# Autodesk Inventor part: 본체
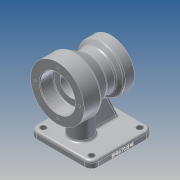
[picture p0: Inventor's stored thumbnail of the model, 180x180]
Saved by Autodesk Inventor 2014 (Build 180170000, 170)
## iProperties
Created: 2019-01
Part Number: 본체
Material: 알루미늄 6061
Document SubType Name: Modeling
Designer: kb542-15
Density: 2.71 g/cm^3
Appearance: 알루미늄 - 평지
Mass: 901.883 g
Surface Area: 599.891 cm^2
Volume: 332.798 cm^3
Author: kb542-15
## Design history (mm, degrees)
sketch "스케치1"
  geometry: L1 (0, 0)-(92, 0); L2 (92, 0)-(92, 92); L3 (92, 92)-(0, 92); L4 (0, 92)-(0, 0)
  constraints: 8 end point, 2 parallel, 1 horizontal, 1 perpendicular
  dimensions: "d0" = 92 distance between parallel lines of L2 L4; "d1" = 92 distance between parallel lines of L1 L3
extrude "돌출1" new body sketch "스케치1" distance "d2" = 10; taper "d3" = 0 deg
fillet "모깎기1" dims "d4" = 10
sketch "스케치3"
  geometry: L1 (82, 92)-(10, 92) reference; L2 (0, 82)-(0, 10) reference; L3 (10, 0)-(82, 0) reference; L4 (92, 10)-(92, 82) reference; C1 r 4.5 at (10, 82); C2 r 4.5 at (82, 82); C3 r 4.5 at (82, 10); C4 r 4.5 at (10, 10); A1 r 10 centre (10, 82) between (10, 92) and (0, 82) reference; A2 r 10 centre (82, 82) between (92, 82) and (82, 92) reference; A3 r 10 centre (82, 10) between (82, 0) and (92, 10) reference; A4 r 10 centre (10, 10) between (0, 10) and (10, 0) reference; 1 further point
  constraints: 4 centre point, 4 coincident, 3 equal radius
  dimensions: "d5" = 9 diameter of C1
extrude "돌출2" cut sketch "스케치3" distance "d6" = 10; taper "d7" = 0 deg
node "작업 평면1"
sketch "스케치4"
  geometry: L1 (-5, 80)-(75, 80); L2 (10, 0)-(82, 0) reference; L3 (0, 10)-(0, 0) reference; L4 (-5, 120)-(20, 120); L5 (20, 120)-(40.785, 108); L6 (40.785, 108)-(54.126, 108); L7 (54.126, 108)-(60, 115); L8 (60, 115)-(75, 115); L9 (-5, 120)-(-5, 106); L10 (-5, 106)-(15, 106); L11 (15, 106)-(15, 96); L12 (15, 96)-(58, 96); L13 (58, 96)-(58, 100); L14 (58, 100)-(75, 100); L15 (75, 100)-(75, 115)
  constraints: 26 end point, 7 parallel, 3 perpendicular, 2 vertical alignment, 1 horizontal
  dimensions: "d8" = 80 distance between parallel lines of L2 L1; "d10" = 5 distance from line of L3 L1.start; "d11" = 80 distance of L1.start L1.end; "d12" = 80 diameter of L4 L1; "d13" = 56 diameter of L6 L1; "d14" = 70 diameter of L8 L1; "d16" = 25 distance of L4.end L4.start; "d17" = 15 distance of L8.end L7.end; "d18" = 30 deg angle of L6 L5; "d19" = 50 deg angle of L6 L7; "d20" = 52 diameter of L10 L1; "d21" = 20 distance between parallel lines of L9 L11; "d22" = 32 diameter of L12 L1; "d23" = 40 diameter of L14 L1; "d24" = 17 distance between parallel lines of L15 L13
revolve "회전1" sketch "스케치4" stored, may be unused: angle "d25" = 90 deg
sketch "스케치5"
  geometry: L1 (0, 82)-(0, 10) reference; L2 (82, 92)-(10, 92) reference; L3 (92, 10)-(92, 82) reference; L4 (10, 0)-(82, 0) reference; C1 r 4.5 at (82, 10) reference; C2 r 4.5 at (10, 82) reference; C3 r 4.5 at (82, 82) reference; C4 r 4.5 at (10, 10) reference; C5 r 16 at (46, 30); A1 r 10 centre (10, 10) between (0, 10) and (10, 0) reference; A2 r 10 centre (10, 82) between (10, 92) and (0, 82) reference; A3 r 10 centre (82, 82) between (92, 82) and (82, 92) reference; A4 r 10 centre (82, 10) between (82, 0) and (92, 10) reference; 1 further point
  constraints: 1 centre point
  dimensions: "d26" = 30 distance from line of C5.centre L4; "d27" = 46 distance from line of C5.centre L1; "d28" = 16 radius of C5
extrude "돌출3" join sketch "스케치5" stored distance "d29" = 10; taper "d30" = 0 deg
node "작업 평면2"
sketch "스케치6"
  geometry: L1 (66.803, 42.104)-(82, 9.514); L2 (92, 0)-(92, 10) reference; 1 further point
  constraints: 2 end point
  dimensions: "d31" = 10 distance from line of L2 L1.end; "d32" = 25 deg angle of L2 L1
feature "리브1" sketch "스케치6" dims "d33" = 1, "d34" = 10, "d35" = 0, "d36" = 0, "d37" = 1, "d38" = 1
sketch "스케치7" dims "d39" = 66
  geometry: C1 r 26 at (0, 0) reference; C2 r 40 at (0, 0) reference; 3 further points
  constraints: 2 vertical alignment, 1 coincident, 2 other
hole "구멍1" sketch "스케치7" at (0, 33) diameter "d40" = 3.242; stored, may be unused: countersink angle "d44" = 90 deg, drill point angle "d46" = 118 deg; dims "d41" = 9, "d42" = 4, "d43" = 2, "d45" = 11
sketch "스케치8" dims "d50" = 55
  geometry: C1 r 35 at (0, 0) reference; 3 further points
  constraints: 2 vertical alignment, 1 coincident, 2 other
hole "구멍2" sketch "스케치8" at (0, -27.5) diameter "d51" = 3.242; stored, may be unused: countersink angle "d55" = 90 deg, drill point angle "d57" = 118 deg; dims "d52" = 9, "d53" = 4, "d54" = 2, "d56" = 11
fillet "모깎기2" dims "d61" = 3
fillet "모깎기3" dims "d62" = 3
fillet "모깎기4" dims "d63" = 1, "d64" = 0.6
chamfer "모따기1" distance "d65" = 1; stored, may be unused: second distance "d66" = 2, angle "d67" = 45 deg
sketch "스케치9" dims "d62" = 3
  geometry: L1 (-6.402, 19.408)-(-6.402, 52.592); L2 (-6.402, 52.592)-(-1.598, 52.592); L3 (-1.598, 52.592)-(-1.598, 19.408); L4 (-1.598, 19.408)-(-6.402, 19.408); L5 (-6.402, 19.408)-(-1.598, 52.592); L6 (-7, -10)-(0, -10) reference; L7 (0, 82)-(0, 72) reference; 1 further point
  constraints: 2 end point, 1 midpoint, 2 other
  dimensions: "d68" = 46 distance from line of L6 point (-4, 36); "d69" = 4 distance from line of L7 point (-4, 36)
feature "엠보싱1" sketch "스케치9" dims "d0" = 92, "d1" = 92, "d70" = 0.5, "d71" = 0
node "솔리드1"
pattern_circular "원형 패턴1" dims angle "d48" = 360 deg
pattern_circular "원형 패턴2" dims angle "d59" = 360 deg
node "투영된 루프1"
